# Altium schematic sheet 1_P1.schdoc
size 309 x 223 mm; Symbol: Sheet-Symbol_A4; Device: Sheet-Symbol_A4; @Page Name: P1; @Create Date: 2023-03-23; @Page Count: 1; @Page No: 1; @Project Name: 12345678; @Schematic Name: Schematic1; @Update Date: 2023-03-23; Company: 嘉立创EDA; Page Size: A2; Version: V1.0
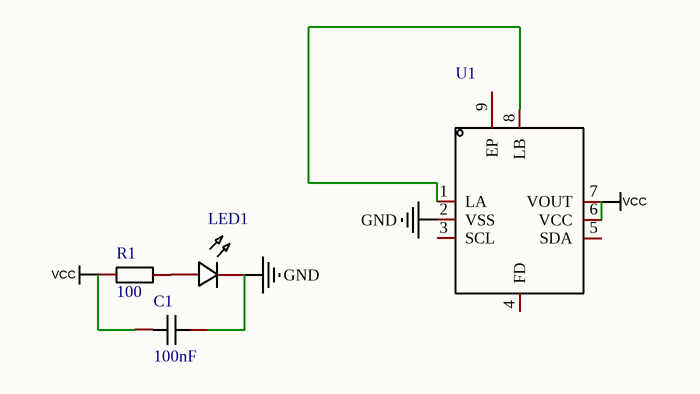
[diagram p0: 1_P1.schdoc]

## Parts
C1  value 100nF  [C0603]  (hidden comment: CAP_0603)
LED1  LED_0603-R  [LED_0603]  (value not drawn)
R1  value 100  [R0603]  (hidden comment: Res_0603)
U1  NT3H1101W0FHKH  [XQFN-8_L1.6-W1.6-P0.50-BR]  (value not drawn)

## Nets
GND: C1.1 LED1.1(C) U1.2(VSS)
VCC: C1.2 R1.1 U1.6(VCC) U1.7(VOUT)
NetLED1_2: LED1.2(A) R1.2
NetU1_1: U1.1(LA) U1.8(LB)

Not connected (* = marked no-connect by the designer): U1 3(SCL) 4(FD) 5(SDA) 9(EP)

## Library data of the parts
C1 = CAP_0603: Symbol: CapAcitance; Convert to PCB: yes
LED1 = LED_0603-R: Symbol: LED_R; Convert to PCB: yes
R1 = Res_0603: Symbol: 电阻; Convert to PCB: yes
U1 = NT3H1101W0FHKH: NT3HSeries3.6V13.56MHzSMTEnergyHarvestingNFCForumType2Tag; Manufacturer: NXP(恩智浦); Add into BOM: yes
